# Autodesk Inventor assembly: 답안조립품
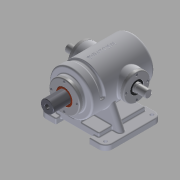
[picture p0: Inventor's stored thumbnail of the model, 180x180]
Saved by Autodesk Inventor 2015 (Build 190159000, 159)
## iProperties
Created: 2015-10
Part Number: 답안조립품
Document SubType Name: Assembly
Designer: youjin13
Mass: 9437.34 g
Surface Area: 4327.34 cm^2
Volume: 2315.26 cm^3
Density: 4.07615 g/cm^3
Author: youjin13
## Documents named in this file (13)
- C:\Users\youjin13\Desktop\351019V1001\답안조립품.iam
- C:\Users\youjin13\Desktop\351019V1001\본체.ipt
- C:\Users\youjin13\Desktop\351019V1001\축 커버.ipt
- C:\Users\youjin13\Desktop\351019V1001\오일실.ipt
- 오일실.ipt
- C:\Users\youjin13\Desktop\351019V1001\M4x0.7.ipt
- C:\Users\youjin13\Desktop\351019V1001\슬라이드 커버.ipt
- C:\Users\youjin13\Desktop\351019V1001\부시.ipt
- C:\Users\youjin13\Desktop\351019V1001\편심축.ipt
- C:\Users\youjin13\Desktop\351019V1001\베어링 6205.ipt
- 베어링 6205.ipt
- C:\Users\youjin13\Desktop\351019V1001\가변스프링.ipt
- C:\Users\youjin13\Desktop\351019V1001\슬라이드.ipt
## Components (13 placed, 2 different names)
1. 가변스프링:1 — Mate:22, Mate:23, Mate:24, Mate:25
2. M4x0.7:3 — Insert:3
3. M4x0.7:4
4. M4x0.7:5
5. M4x0.7:6
6. M4x0.7:1 — Insert:1
7. M4x0.7:7
8. M4x0.7:8
9. M4x0.7:9
10. M4x0.7:2 — Insert:2
11. M4x0.7:10
12. M4x0.7:11
13. M4x0.7:12
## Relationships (7: Mate 4, Insert 3)
- Insert:1: M4x0.7:1
- Insert:2: M4x0.7:2
- Insert:3: M4x0.7:3
- Mate:22: 가변스프링:1
- Mate:23: 가변스프링:1
- Mate:24: 가변스프링:1
- Mate:25: 가변스프링:1
